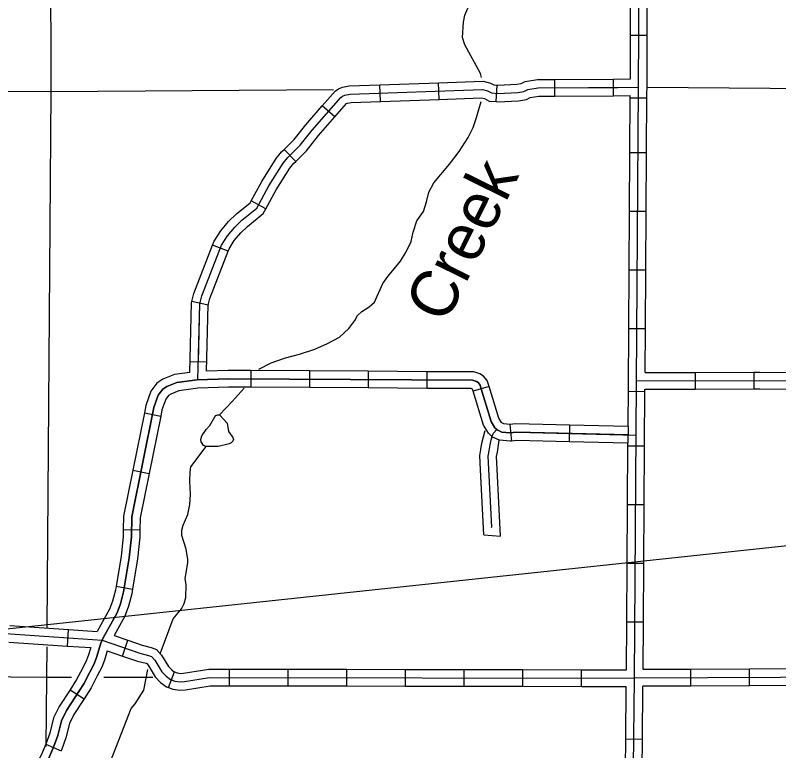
# Model space of a CAD drawing. Extents: x 1373862 to 1376999, y 1168398 to 1170455.
# Drawn here: x 1375659.7 to 1375797.1, y 1169098.5 to 1169230.9 of the extents above; entities that cross this region are included whole.
import ezdxf

# ---------------------------------------------------------------- set-up
doc = ezdxf.new("R2010")
doc.units = 0
for name, color, linetype in [('Level 32', 7, 'Continuous'), ('Level 35', 7, 'Continuous'), ('Level 45', 7, 'Continuous'), ('Level 5', 7, 'Continuous'), ('Level 8', 7, 'Continuous'), ('R_Draft', 7, 'Continuous')]:
    doc.layers.add(name, color=color, linetype=linetype)

msp = doc.modelspace()

# ---------------------------------------------------------------- linework, layer by layer
at = {"layer": 'Level 32'}
for p, q in [((1375770.41, 1169227.28), (1375773.41, 1169227.27)), ((1375756.77, 1169216.31), (1375756.75, 1169219.31)), ((1375767.33, 1169216.39), (1375767.3, 1169219.39)), ((1375725.39, 1169215.37), (1375725.29, 1169218.37)), ((1375735.95, 1169215.73), (1375735.84, 1169218.73)), ((1375746.23, 1169215.32), (1375746.42, 1169218.31)), ((1375770.35, 1169216.01), (1375773.35, 1169215.99)), ((1375717.19, 1169212.58), (1375714.93, 1169214.55)), ((1375710.15, 1169204.57), (1375708.05, 1169206.71)), ((1375770.28, 1169206.17), (1375773.28, 1169206.15)), ((1375704.79, 1169196.02), (1375702.15, 1169197.46)), ((1375770.21, 1169195.61), (1375773.21, 1169195.59)), ((1375697.98, 1169188.38), (1375695.18, 1169189.46)), ((1375770.14, 1169185.05), (1375773.14, 1169185.03)), ((1375694.4, 1169178.66), (1375691.48, 1169179.37)), ((1375770.07, 1169174.49), (1375773.07, 1169174.47)), ((1375694.14, 1169168.42), (1375691.14, 1169168.5)), ((1375702.08, 1169166.91), (1375702.07, 1169163.91)), ((1375712.64, 1169166.84), (1375712.63, 1169163.84)), ((1375723.2, 1169166.77), (1375723.19, 1169163.77)), ((1375733.76, 1169166.7), (1375733.74, 1169163.7)), ((1375782.03, 1169166.56), (1375782.04, 1169163.56)), ((1375792.59, 1169166.59), (1375792.6, 1169163.59)), ((1375744.93, 1169164.05), (1375742.06, 1169163.17)), ((1375770, 1169163.17), (1375772.99, 1169163.15)), ((1375682.92, 1169159.32), (1375685.86, 1169158.72)), ((1375748.66, 1169157.19), (1375749, 1169154.21)), ((1375759.42, 1169157.08), (1375759.35, 1169154.09)), ((1375769.97, 1169156.83), (1375769.9, 1169153.83)), ((1375769.93, 1169153.37), (1375772.93, 1169153.35)), ((1375680.83, 1169148.97), (1375683.77, 1169148.37)), ((1375769.85, 1169142.81), (1375772.85, 1169142.79)), ((1375679.11, 1169138.3), (1375682.11, 1169138.24)), ((1375769.78, 1169132.25), (1375772.78, 1169132.23)), ((1375677.82, 1169128.06), (1375680.78, 1169127.56)), ((1375769.71, 1169121.69), (1375772.71, 1169121.67)), ((1375669.08, 1169117.3), (1375669.28, 1169120.29)), ((1375678.98, 1169115.51), (1375679.97, 1169118.34)), ((1375687.26, 1169109.83), (1375688.32, 1169112.64)), ((1375698.23, 1169110.16), (1375698.23, 1169113.16)), ((1375708.79, 1169110.14), (1375708.79, 1169113.14)), ((1375719.35, 1169110.12), (1375719.35, 1169113.12)), ((1375729.91, 1169110.11), (1375729.91, 1169113.11)), ((1375740.47, 1169110.09), (1375740.47, 1169113.09)), ((1375751.03, 1169110.07), (1375751.03, 1169113.07)), ((1375761.59, 1169110.05), (1375761.59, 1169113.05)), ((1375781.24, 1169110.1), (1375781.23, 1169113.1)), ((1375791.8, 1169110.14), (1375791.79, 1169113.14)), ((1375669.54, 1169109.44), (1375672.06, 1169107.81)), ((1375665.19, 1169099.63), (1375667.95, 1169098.46)), ((1375769.52, 1169100.58), (1375772.52, 1169100.54))]:
    msp.add_line(p, q, dxfattribs=at)
for points in [[(1375771.83, 1169217.93), (1375772.04, 1169258.18)], [(1375770.41, 1169227.28), (1375770.46, 1169237.84)], [(1375773.41, 1169227.27), (1375773.46, 1169237.83)], [(1375770.37, 1169219.41), (1375770.41, 1169227.28)], [(1375773.35, 1169216.71), (1375773.36, 1169217.92), (1375773.41, 1169227.27)], [(1375746.42, 1169218.31), (1375746.54, 1169218.31), (1375749.93, 1169218.47), (1375750.73, 1169218.6), (1375751.42, 1169218.95), (1375753.67, 1169219.29), (1375756.75, 1169219.31)], [(1375756.75, 1169219.31), (1375767.3, 1169219.39)], [(1375767.3, 1169219.39), (1375770.37, 1169219.41)], [(1375692.64, 1169168.46), (1375692.92, 1169178.92), (1375693.27, 1169180.35), (1375696.81, 1169189.51), (1375697.88, 1169191.18), (1375699.17, 1169192.74), (1375700.48, 1169193.99), (1375703.15, 1169196.15), (1375705.34, 1169200.18), (1375707.88, 1169204.22), (1375708.73, 1169205.27), (1375710.98, 1169207.49), (1375713.1, 1169210.16), (1375718.25, 1169216.09), (1375718.57, 1169216.31), (1375719, 1169216.49), (1375719.94, 1169216.68), (1375743.73, 1169217.5), (1375744.66, 1169217.27), (1375745.4, 1169216.88), (1375746.52, 1169216.8), (1375750.09, 1169216.97), (1375751.21, 1169217.16), (1375751.89, 1169217.51), (1375753.79, 1169217.79), (1375768.11, 1169217.9)], [(1375714.93, 1169214.55), (1375717.24, 1169217.21), (1375717.84, 1169217.63), (1375718.56, 1169217.93), (1375719.77, 1169218.18), (1375725.29, 1169218.37)], [(1375725.29, 1169218.37), (1375735.84, 1169218.73)], [(1375735.84, 1169218.73), (1375743.89, 1169219.01), (1375745.2, 1169218.68), (1375745.82, 1169218.35), (1375746.42, 1169218.31)], [(1375770.29, 1169037.2), (1375771.11, 1169111.53), (1375771.83, 1169217.93)], [(1375756.77, 1169216.31), (1375767.33, 1169216.39)], [(1375767.33, 1169216.39), (1375770.35, 1169216.41)], [(1375770.28, 1169206.17), (1375770.35, 1169216.41)], [(1375773.28, 1169206.15), (1375773.35, 1169216.71)], [(1375717.19, 1169212.58), (1375719.26, 1169214.96), (1375719.29, 1169214.99), (1375719.45, 1169215.05), (1375720.12, 1169215.19), (1375725.39, 1169215.37)], [(1375725.39, 1169215.37), (1375735.95, 1169215.73)], [(1375735.95, 1169215.73), (1375743.57, 1169216), (1375744.11, 1169215.86), (1375744.98, 1169215.4), (1375746.23, 1169215.32)], [(1375746.23, 1169215.32), (1375746.51, 1169215.3), (1375750.25, 1169215.48), (1375751.68, 1169215.72), (1375752.35, 1169216.06), (1375753.9, 1169216.29), (1375756.77, 1169216.31)], [(1375708.05, 1169206.71), (1375709.86, 1169208.5), (1375711.95, 1169211.12), (1375714.93, 1169214.55)], [(1375710.15, 1169204.57), (1375712.1, 1169206.49), (1375714.25, 1169209.2), (1375717.19, 1169212.58)], [(1375702.15, 1169197.46), (1375704.05, 1169200.94), (1375706.65, 1169205.1), (1375707.62, 1169206.28), (1375708.05, 1169206.71)], [(1375770.21, 1169195.61), (1375770.28, 1169206.17)], [(1375773.21, 1169195.59), (1375773.28, 1169206.15)], [(1375704.79, 1169196.02), (1375706.64, 1169199.42), (1375709.1, 1169203.35), (1375709.84, 1169204.26), (1375710.15, 1169204.57)], [(1375695.18, 1169189.46), (1375695.46, 1169190.19), (1375696.66, 1169192.07), (1375698.07, 1169193.76), (1375699.49, 1169195.12), (1375701.97, 1169197.13), (1375702.15, 1169197.46)], [(1375697.98, 1169188.38), (1375698.15, 1169188.83), (1375699.09, 1169190.3), (1375700.26, 1169191.71), (1375701.47, 1169192.86), (1375704.32, 1169195.17), (1375704.79, 1169196.02)], [(1375770.14, 1169185.05), (1375770.21, 1169195.61)], [(1375773.14, 1169185.03), (1375773.21, 1169195.59)], [(1375691.48, 1169179.37), (1375691.83, 1169180.8), (1375695.18, 1169189.46)], [(1375694.4, 1169178.66), (1375694.7, 1169179.9), (1375697.98, 1169188.38)], [(1375770.07, 1169174.49), (1375770.14, 1169185.05)], [(1375773.07, 1169174.47), (1375773.14, 1169185.03)], [(1375691.09, 1169166.56), (1375691.42, 1169179.12), (1375691.48, 1169179.37)], [(1375694.1, 1169166.78), (1375694.41, 1169178.72), (1375694.4, 1169178.66)], [(1375770, 1169163.93), (1375770.07, 1169174.49)], [(1375773.01, 1169166.54), (1375773.07, 1169174.47)], [(1375702.08, 1169166.91), (1375698.02, 1169166.94), (1375694.1, 1169166.78)], [(1375712.64, 1169166.84), (1375702.08, 1169166.91)], [(1375691.09, 1169166.56), (1375688.34, 1169166.21), (1375686.26, 1169165.34), (1375685.19, 1169164.66), (1375684.09, 1169163.21), (1375683.19, 1169160.64), (1375682.92, 1169159.32)], [(1375723.2, 1169166.77), (1375712.64, 1169166.84)], [(1375733.76, 1169166.7), (1375723.2, 1169166.77)], [(1375744.93, 1169164.05), (1375744.6, 1169165.11), (1375743.93, 1169165.9), (1375743.28, 1169166.29), (1375742.2, 1169166.65), (1375733.76, 1169166.7)], [(1375773.01, 1169166.54), (1375782.03, 1169166.56)], [(1375782.03, 1169166.56), (1375792.59, 1169166.59)], [(1375792.59, 1169166.59), (1375793.64, 1169166.6), (1375803.16, 1169166.55)], [(1375769.94, 1169155.33), (1375749.85, 1169155.81), (1375748.7, 1169155.68), (1375747.22, 1169155.83), (1375746.42, 1169156.21), (1375745.99, 1169156.58), (1375745.31, 1169157.72), (1375743.25, 1169164.38), (1375742.95, 1169164.74), (1375742.65, 1169164.92), (1375741.95, 1169165.15), (1375698.04, 1169165.44), (1375692.39, 1169165.21), (1375688.73, 1169164.74), (1375686.96, 1169164.01), (1375686.22, 1169163.54), (1375685.42, 1169162.49), (1375684.64, 1169160.24), (1375680.65, 1169140.55), (1375680.58, 1169136.99), (1375680.21, 1169133.22), (1375679.17, 1169127.04), (1375678.6, 1169124.91), (1375678.01, 1169123.3), (1375675.5, 1169118.77), (1375675.07, 1169117.83), (1375674.31, 1169115.26), (1375673.87, 1169114.13), (1375673.1, 1169112.6), (1375672.02, 1169110.51), (1375668.91, 1169105.7), (1375668, 1169103.87), (1375667.34, 1169101.2), (1375666.59, 1169099.11), (1375665.69, 1169096.98)], [(1375771.48, 1169165.06), (1375793.64, 1169165.13), (1375816.8, 1169165), (1375834.26, 1169165.46)], [(1375691.72, 1169163.61), (1375689.12, 1169163.28), (1375687.65, 1169162.67), (1375687.25, 1169162.42), (1375686.76, 1169161.78), (1375686.09, 1169159.85), (1375685.86, 1169158.72)], [(1375702.07, 1169163.91), (1375698.07, 1169163.93), (1375692.52, 1169163.72), (1375691.72, 1169163.61)], [(1375712.63, 1169163.84), (1375702.07, 1169163.91)], [(1375723.19, 1169163.77), (1375712.63, 1169163.84)], [(1375733.74, 1169163.7), (1375723.19, 1169163.77)], [(1375742.06, 1169163.17), (1375741.93, 1169163.57), (1375741.7, 1169163.65), (1375733.74, 1169163.7)], [(1375749, 1169154.21), (1375748.71, 1169154.18), (1375746.82, 1169154.37), (1375745.58, 1169154.94), (1375744.83, 1169155.61), (1375743.93, 1169157.1), (1375742.06, 1169163.17)], [(1375748.7, 1169157.19), (1375747.62, 1169157.3), (1375747.25, 1169157.47), (1375747.16, 1169157.55), (1375746.68, 1169158.34), (1375744.93, 1169164.05)], [(1375769.95, 1169156.81), (1375770, 1169163.93)], [(1375772.93, 1169153.35), (1375772.99, 1169163.54)], [(1375772.99, 1169163.54), (1375782.04, 1169163.56)], [(1375782.04, 1169163.56), (1375792.6, 1169163.59)], [(1375792.6, 1169163.59), (1375793.64, 1169163.6), (1375803.15, 1169163.55)], [(1375682.92, 1169159.32), (1375680.83, 1169148.97)], [(1375685.86, 1169158.72), (1375683.77, 1169148.37)], [(1375759.42, 1169157.08), (1375749.78, 1169157.31), (1375748.66, 1169157.19)], [(1375769.97, 1169156.83), (1375759.42, 1169157.08)], [(1375759.35, 1169154.09), (1375749.91, 1169154.31), (1375749, 1169154.21)], [(1375769.9, 1169153.83), (1375759.35, 1169154.09)], [(1375769.85, 1169142.81), (1375769.93, 1169153.81)], [(1375772.85, 1169142.79), (1375772.93, 1169153.35)], [(1375680.83, 1169148.97), (1375679.16, 1169140.72), (1375679.11, 1169138.3)], [(1375683.77, 1169148.37), (1375682.15, 1169140.39), (1375682.11, 1169138.24)], [(1375769.78, 1169132.25), (1375769.85, 1169142.81)], [(1375772.78, 1169132.23), (1375772.85, 1169142.79)], [(1375679.11, 1169138.3), (1375679.08, 1169137.08), (1375678.72, 1169133.42), (1375677.82, 1169128.06)], [(1375682.11, 1169138.24), (1375682.08, 1169136.9), (1375681.69, 1169133.02), (1375680.78, 1169127.56)], [(1375769.71, 1169121.69), (1375769.78, 1169132.25)], [(1375772.71, 1169121.67), (1375772.78, 1169132.23)], [(1375677.82, 1169128.06), (1375677.7, 1169127.35), (1375677.17, 1169125.36), (1375676.65, 1169123.93), (1375674.44, 1169119.95)], [(1375680.78, 1169127.56), (1375680.64, 1169126.72), (1375680.04, 1169124.46), (1375679.38, 1169122.68), (1375677.47, 1169119.22)], [(1375769.65, 1169113.03), (1375769.71, 1169121.69)], [(1375772.65, 1169113.06), (1375772.71, 1169121.67)], [(1375658.74, 1169121), (1375669.28, 1169120.29)], [(1375669.28, 1169120.29), (1375674.44, 1169119.95)], [(1375650.9, 1169120.03), (1375675.32, 1169118.38), (1375682.11, 1169116), (1375683.68, 1169115.63), (1375684.22, 1169115.41), (1375684.81, 1169114.76), (1375686.08, 1169112.68), (1375686.83, 1169111.89), (1375687.63, 1169111.29), (1375688.42, 1169111), (1375689.38, 1169110.86), (1375690.14, 1169110.91), (1375694.62, 1169111.67), (1375771.11, 1169111.53)], [(1375677.47, 1169119.22), (1375679.97, 1169118.34)], [(1375658.54, 1169118.01), (1375669.08, 1169117.3)], [(1375679.97, 1169118.34), (1375682.53, 1169117.44), (1375684.13, 1169117.06), (1375685.1, 1169116.68), (1375686.01, 1169115.66), (1375687.28, 1169113.6), (1375687.83, 1169113.01), (1375688.36, 1169112.62), (1375688.32, 1169112.64)], [(1375669.08, 1169117.3), (1375673.26, 1169117.02)], [(1375673.26, 1169117.02), (1375672.89, 1169115.74), (1375672.5, 1169114.74), (1375671.77, 1169113.29), (1375670.72, 1169111.27), (1375669.54, 1169109.44)], [(1375676.23, 1169116.47), (1375675.73, 1169114.77), (1375675.25, 1169113.52), (1375674.44, 1169111.92), (1375673.32, 1169109.76), (1375672.06, 1169107.81)], [(1375676.23, 1169116.47), (1375678.98, 1169115.51)], [(1375678.98, 1169115.51), (1375681.69, 1169114.56), (1375683.23, 1169114.2), (1375683.34, 1169114.15), (1375683.6, 1169113.86), (1375684.88, 1169111.77), (1375685.83, 1169110.76), (1375686.91, 1169109.96), (1375687.26, 1169109.83)], [(1375688.32, 1169112.64), (1375688.79, 1169112.46), (1375689.44, 1169112.37), (1375689.97, 1169112.4), (1375694.5, 1169113.17), (1375698.23, 1169113.16)], [(1375698.23, 1169113.16), (1375708.79, 1169113.14)], [(1375708.79, 1169113.14), (1375719.35, 1169113.12)], [(1375719.35, 1169113.12), (1375729.91, 1169113.11)], [(1375729.91, 1169113.11), (1375740.47, 1169113.09)], [(1375740.47, 1169113.09), (1375751.03, 1169113.07)], [(1375751.03, 1169113.07), (1375761.59, 1169113.05)], [(1375761.59, 1169113.05), (1375769.65, 1169113.03)], [(1375781.23, 1169113.1), (1375772.65, 1169113.06)], [(1375791.79, 1169113.14), (1375781.23, 1169113.1)], [(1375802.35, 1169113.18), (1375791.79, 1169113.14)], [(1375822.65, 1169006.32), (1375823.65, 1169111.74), (1375771.11, 1169111.53)], [(1375669.54, 1169109.44), (1375667.6, 1169106.44), (1375666.58, 1169104.39), (1375665.9, 1169101.63), (1375665.19, 1169099.65), (1375665.19, 1169099.63)], [(1375687.26, 1169109.83), (1375688.05, 1169109.53), (1375689.32, 1169109.36), (1375690.31, 1169109.42), (1375694.75, 1169110.17), (1375698.23, 1169110.16)], [(1375698.23, 1169110.16), (1375708.79, 1169110.14)], [(1375708.79, 1169110.14), (1375719.35, 1169110.12)], [(1375719.35, 1169110.12), (1375729.91, 1169110.11)], [(1375729.91, 1169110.11), (1375740.47, 1169110.09)], [(1375740.47, 1169110.09), (1375751.03, 1169110.07)], [(1375751.03, 1169110.07), (1375761.59, 1169110.05)], [(1375761.59, 1169110.05), (1375769.63, 1169110.03)], [(1375769.52, 1169100.58), (1375769.63, 1169110.03)], [(1375772.52, 1169100.54), (1375772.63, 1169110.06)], [(1375781.24, 1169110.1), (1375772.63, 1169110.06)], [(1375791.8, 1169110.14), (1375781.24, 1169110.1)], [(1375802.36, 1169110.18), (1375791.8, 1169110.14)], [(1375672.06, 1169107.81), (1375670.21, 1169104.96), (1375669.42, 1169103.35), (1375668.78, 1169100.76), (1375667.99, 1169098.56), (1375667.95, 1169098.46)], [(1375665.19, 1169099.63), (1375664.34, 1169097.64), (1375663.67, 1169096.46), (1375662.47, 1169094.82), (1375661.32, 1169092.07), (1375660.64, 1169090.04)], [(1375769.4, 1169090.02), (1375769.52, 1169100.58)], [(1375772.4, 1169089.98), (1375772.52, 1169100.54)]]:
    msp.add_lwpolyline(points, dxfattribs=at)
at = {"layer": 'Level 35'}
for points in [[(1375743.56, 1169219.69), (1375743.39, 1169220.41), (1375740.57, 1169225.54), (1375740.14, 1169226.85), (1375740.34, 1169229.62), (1375740.59, 1169230.91), (1375741.1, 1169232.15), (1375741.9, 1169233.46)], [(1375703.5, 1169167.18), (1375705.71, 1169168.32), (1375708.29, 1169169.22), (1375710.81, 1169169.88), (1375713.57, 1169170.78), (1375715.88, 1169171.78), (1375718, 1169172.9), (1375719.71, 1169174.48), (1375720.8, 1169175.91), (1375721.29, 1169176.85), (1375722.07, 1169177.56), (1375723.38, 1169178.41), (1375724.3, 1169179.24), (1375725.84, 1169182.6), (1375726.71, 1169183.83), (1375729.01, 1169186.61), (1375730.04, 1169188.28), (1375730.95, 1169190.17), (1375731.3, 1169191.82), (1375731.93, 1169193.89), (1375733.12, 1169195.56), (1375733.7, 1169197.29), (1375734.09, 1169199.04), (1375734.98, 1169200.71), (1375737.84, 1169204.07), (1375739.57, 1169206.33), (1375741.17, 1169208.89), (1375742.06, 1169210.66), (1375742.67, 1169212.49), (1375743.52, 1169215.35)], [(1375696.43, 1169158.92), (1375698.71, 1169161.32), (1375700.9, 1169163.75)], [(1375694.03, 1169153.25), (1375693.57, 1169153.41), (1375693.13, 1169154.05), (1375693.08, 1169154.51), (1375693.24, 1169155.17), (1375694.03, 1169156.3), (1375694.71, 1169157.02), (1375695.58, 1169158.55), (1375695.79, 1169158.79), (1375696.11, 1169158.94), (1375696.43, 1169158.92), (1375697.79, 1169157.41), (1375698.06, 1169155.95), (1375698.81, 1169154.85), (1375698.95, 1169154.47), (1375698.85, 1169154.19), (1375698.55, 1169153.91), (1375698.15, 1169153.74), (1375696.2, 1169153.25), (1375694.03, 1169153.25)], [(1375690.42, 1169128.3), (1375690.27, 1169129.46), (1375690.71, 1169132.29), (1375690.71, 1169132.87), (1375690.41, 1169134.73), (1375689.65, 1169137.19), (1375689.65, 1169138.17), (1375689.88, 1169139.07), (1375690.75, 1169140.98), (1375691.12, 1169142.79), (1375691.22, 1169144.59), (1375691.11, 1169146.98), (1375691.17, 1169148.7), (1375691.29, 1169149.56), (1375694.03, 1169153.25)], [(1375685.78, 1169115.88), (1375688.12, 1169122.19), (1375689.59, 1169124), (1375690.1, 1169124.99), (1375690.4, 1169126.05), (1375690.42, 1169128.3)], [(1375665.39, 1169079.09), (1375667.68, 1169080.79), (1375668.41, 1169083.16), (1375668.87, 1169085.41), (1375669.47, 1169086.13), (1375670.92, 1169086.7), (1375672.56, 1169087.62), (1375673.85, 1169088.79), (1375674.68, 1169090.3), (1375675.39, 1169092.17), (1375675.54, 1169093.29), (1375680.56, 1169106.04), (1375681.27, 1169106.9), (1375682.8, 1169109.38), (1375683.57, 1169113.1)]]:
    msp.add_lwpolyline(points, dxfattribs=at)
at = {"layer": 'Level 45'}
for points in [[(1375692.56, 1169165.22), (1375692.92, 1169178.92), (1375693.27, 1169180.35), (1375696.81, 1169189.51), (1375697.88, 1169191.18), (1375699.17, 1169192.74), (1375700.48, 1169193.99), (1375703.15, 1169196.15), (1375705.34, 1169200.18), (1375707.88, 1169204.22), (1375708.73, 1169205.27), (1375710.98, 1169207.49), (1375713.1, 1169210.16), (1375718.25, 1169216.09), (1375718.57, 1169216.31), (1375719, 1169216.49), (1375719.94, 1169216.68), (1375743.73, 1169217.5), (1375744.66, 1169217.27), (1375745.4, 1169216.88), (1375746.52, 1169216.8), (1375750.09, 1169216.97), (1375751.21, 1169217.16), (1375751.89, 1169217.51), (1375753.79, 1169217.79), (1375771.83, 1169217.93)], [(1375665.69, 1169096.98), (1375666.59, 1169099.11), (1375667.34, 1169101.2), (1375668, 1169103.87), (1375668.91, 1169105.7), (1375672.02, 1169110.51), (1375673.1, 1169112.6), (1375673.87, 1169114.13), (1375674.31, 1169115.26), (1375675.07, 1169117.83), (1375675.5, 1169118.77), (1375678.01, 1169123.3), (1375678.6, 1169124.91), (1375679.17, 1169127.04), (1375680.21, 1169133.22), (1375680.58, 1169136.99), (1375680.65, 1169140.55), (1375684.64, 1169160.24), (1375685.42, 1169162.49), (1375686.22, 1169163.54), (1375686.96, 1169164.01), (1375688.73, 1169164.74), (1375692.39, 1169165.21), (1375698.04, 1169165.44), (1375741.95, 1169165.15), (1375742.65, 1169164.92), (1375742.95, 1169164.74), (1375743.25, 1169164.38), (1375745.31, 1169157.72), (1375745.99, 1169156.58), (1375746.42, 1169156.21), (1375747.22, 1169155.83), (1375748.7, 1169155.68), (1375749.85, 1169155.81), (1375771.41, 1169155.3)], [(1375743.39, 1169149.03), (1375743.26, 1169151.62), (1375743.47, 1169152.71), (1375743.64, 1169153.86), (1375744.22, 1169156.14)], [(1375745.25, 1169138.76), (1375745.43, 1169138.74), (1375744.77, 1169151.51), (1375744.95, 1169152.46), (1375745.11, 1169153.56), (1375745.33, 1169154.43), (1375745.69, 1169155.56), (1375746.42, 1169156.38)], [(1375746.39, 1169149.18), (1375746.27, 1169151.41), (1375746.43, 1169152.21), (1375746.75, 1169154.4)], [(1375744, 1169137.36), (1375747.02, 1169137.09), (1375746.39, 1169149.18)], [(1375744, 1169137.36), (1375743.39, 1169149.03)], [(1375650.9, 1169120.03), (1375675.32, 1169118.38), (1375682.11, 1169116), (1375683.68, 1169115.63), (1375684.22, 1169115.41), (1375684.81, 1169114.76), (1375686.08, 1169112.68), (1375686.83, 1169111.89), (1375687.63, 1169111.29), (1375688.42, 1169111), (1375689.38, 1169110.86), (1375690.14, 1169110.91), (1375694.62, 1169111.67), (1375771.11, 1169111.53)]]:
    msp.add_lwpolyline(points, dxfattribs=at)
at = {"layer": 'Level 5'}
for points in [[(1375665.91, 1169292.45), (1375666.1, 1169217.14)], [(1375666.1, 1169217.14), (1375665.37, 1169120.58)], [(1375665.34, 1169117.19), (1375665.3, 1169111.72), (1375665.2, 1169099.23)], [(1375562.5, 1169112.68), (1375665.3, 1169111.72), (1375669.81, 1169111.71)], [(1375675.65, 1169111.7), (1375684.47, 1169111.69)]]:
    msp.add_lwpolyline(points, dxfattribs=at)
at = {"layer": 'Level 8'}
for points in [[(1375561.64, 1169217.86), (1375666.1, 1169217.14)], [(1375773.39, 1169217.91), (1375876.71, 1169217.11)], [(1375666.1, 1169217.14), (1375716.97, 1169217.52)]]:
    msp.add_lwpolyline(points, dxfattribs=at)
at = {"layer": 'R_Draft'}
msp.add_line((1376323.89, 1169191.59), (1375443, 1169097.32), dxfattribs=at)

# ---------------------------------------------------------------- texts
at = {"layer": 'Level 35'}
msp.add_text('Creek', height=8.44, rotation=63.7598, dxfattribs=at).set_placement((1375737.1, 1169175.08))

doc.saveas('drawing.dxf')
